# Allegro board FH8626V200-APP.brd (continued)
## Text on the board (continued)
DISPLAY_TOP: FIGURE | SIZE | 10.0 | 12.0 | 20.0 | 24.0 | 28.0 | 36.0 | 40.0 | 44.0 | 50.0 | 60.0 | 63.0 | 95.0 | 120.0 | 52.0 | 53.0 | 62.99 | 65.0 | 134.0 | 100.0x25.0 | 220.0x60.0 | DRILL CHART: TOP to BOTTOM | ALL UNITS ARE IN MILS | PLATED | NON-PLATED | QTY | 1656 | 7 | 10 | 4 | 2 | 8 | 49 | 52 | 6 | 1 | 3
